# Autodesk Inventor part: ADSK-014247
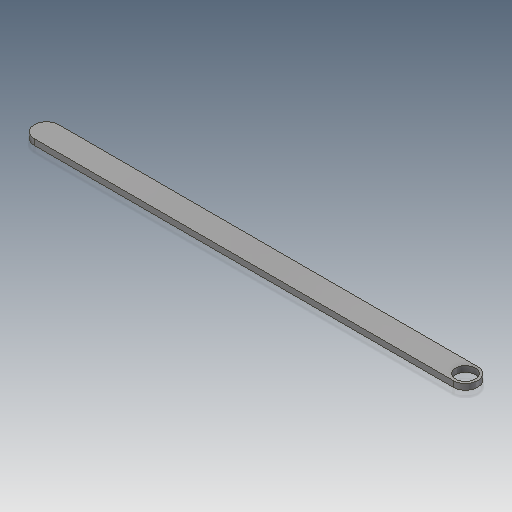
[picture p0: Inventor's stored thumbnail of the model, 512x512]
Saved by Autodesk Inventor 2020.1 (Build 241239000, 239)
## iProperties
Created: 2019-10
Part Number: ADSK-014247
Material: 1.0501 C35
Document SubType Name: Modeling
Designer: lutzd
Mass: 4119 g
Surface Area: 1116.33 cm^2
Volume: 525.382 cm^3
Density: 7.84 g/cm^3
Appearance: Stahl
VLDS_Profile: Default Part
VLDS_TimeStamp: 2016-07-29
VLDS_FailCnt: 0
VLDS_AcceptCnt: 0
Dimensions: 911,5x50x12 mm
Mass: 4,119 kg
DocNumber: ADSK-014247
Folder: 01 - Themengebiete\Simplification\01 - Packaging machine\
VDS_Category: 3D Komponenten
VDS_NumSchm: Autodesk
Title: connection
Author: lutzd
Revision Number: -
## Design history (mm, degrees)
sketch "Skizze1"
  geometry: L1 (-430.75, 0)-(430.75, 0); L2 (-430.75, -25)-(430.75, -25); L3 (430.75, 25)-(-430.75, 25); A1 r 25 centre (-430.75, 0) between (-430.75, 25) and (-430.75, -25); A2 r 25 centre (430.75, 0) between (430.75, -25) and (430.75, 25); 1 further point
  constraints: 8 end point, 4 point on circle, 4 tangent, 2 centre point, 1 horizontal, 1 midpoint, 1 parallel
  dimensions: "d0" = 430.75 distance of point (0, 0) L1.end; "d1" = 50 diameter of A2
extrude "Extrusion1" new body sketch "Skizze1" stored distance "d2" = 12; taper "d3" = 0 deg
sketch "Skizze2"
  geometry: A1 r 25 centre (430.75, 0) between (430.75, -25) and (430.75, 25) reference; 2 further points
  constraints: 1 coincident
hole "Bohrung1" sketch "Skizze2" at (430.75, 0) diameter "d4" = 40; stored, may be unused: countersink angle "d8" = 90 deg, drill point angle "d10" = 118 deg; dims "d5" = 6, "d6" = 10, "d7" = 5.7, "d9" = 8
node "Volumenkörper1"
